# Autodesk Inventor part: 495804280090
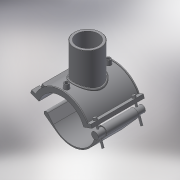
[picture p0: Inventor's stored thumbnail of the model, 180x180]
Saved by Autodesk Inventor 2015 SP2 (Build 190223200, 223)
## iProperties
Created: 2017-07
Part Number: 495804280090
Material: Generic
Description: PLASSON BRANCH SADDLE 280-90
Document SubType Name: Modeling
Designer: KIM
Density: 1 g/cm^3
Appearance: Default
Author: KIM
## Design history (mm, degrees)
derived "495804.ipt"
feature "Solid1::495804.ipt"
feature "Solid2::495804.ipt"
tag "TaggingFeature1"
body "Solid1"
body "Solid2"
other parameters: "d2" = 366.6, "d4" = 176, "d5" = 0, "d6" = 0.1, "d8" = 0, "d19" = 6, "d20" = 6, "d21" = 105.6, "d23" = 0, "d24" = 52.8, "d26" = 0, "d27" = 3, "d28" = 3, "d29" = 3, "d30" = 93.33333, "d31" = 6, "d32" = 0, "d33" = 0, "d34" = 0.6, "d40" = 161.2, "d41" = 99, "d43" = 0, "d45" = 0, "d50" = 0, "d70" = 15, "d72" = 0, "d73" = 6, "d75" = 5, "d76" = 0, "d77" = 14, "d79" = 15, "d80" = 70.4, "d82" = 5 deg, "d84" = 4, "d85" = 14, "d86" = 0, "d87" = 3, "d88" = 0, "d89" = 1, "d90" = 1, "d91" = 140.8, "d92" = 0, "d93" = 0.5, "d94" = 147.36842, "d96" = 316.2, "d97" = 3.52, "d98" = 0, "d102" = 2.7, "d103" = 72, "d105" = 0, "d109" = -35, "d117" = 0.9, "d120" = 140 deg, "d121" = 24.228, "d122" = 20 deg, "d124" = 186, "d126" = 0, "d143" = 294, "d150" = 50.4, "d159" = 6, "d161" = 7, "d162" = 105.6, "d163" = 0, "d167" = 56, "d168" = 140.90909, "d173" = 1, "d176" = 20 deg, "d177" = 19.6, "d180" = 0, "d185" = 57.2, "d186" = 57.2, "d187" = 155, "d188" = 9, "d189" = 19.6, "d190" = 0, "d191" = 232.5, "d200" = 15, "d202" = 0, "d216" = 158.4, "d217" = 0, "d221" = 65.12, "d222" = 19.6, "d223" = 11.76, "d225" = 11.76, "d227" = 40.32, "d230" = 168, "d236" = 20 deg, "d237" = 162, "d238" = 20 deg, "d239" = 19.6, "B_" = 282, "H_" = 105, "L_" = 176, "d_t" = 6, "d148" = 7, "d160" = 7
